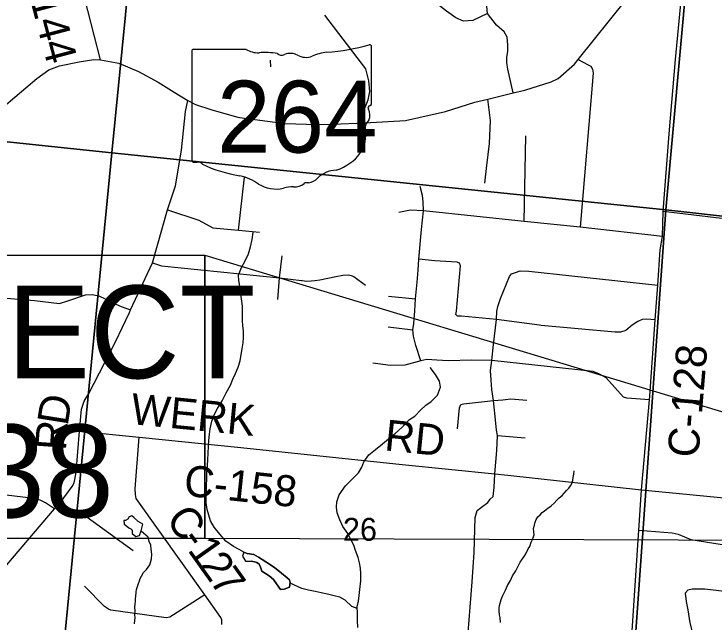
# Model space of a CAD drawing. Extents: x 0 to 34, y 0 to 22.
# Drawn here: x 4.767 to 6.05, y 18.737 to 19.852 of the extents above; entities that cross this region are included whole.
import ezdxf

# ---------------------------------------------------------------- set-up
doc = ezdxf.new("R2010")
doc.units = 0
for name, color, linetype in [('GM_X_Corporation', 7, 'Continuous'), ('GM_X_County_Road', 7, 'Continuous'), ('GM_X_County_Road_Text', 7, 'Continuous'), ('GM_X_Minor_Lake', 7, 'Continuous'), ('GM_X_Minor_River', 7, 'Continuous'), ('GM_X_Section_Text', 7, 'Continuous'), ('GM_X_State_Location', 7, 'Continuous'), ('GM_X_State_Route', 7, 'Continuous'), ('GM_X_State_Shield', 7, 'Continuous'), ('GM_X_Township_Road', 7, 'Continuous'), ('SH_Masking', 7, 'Continuous'), ('SH_Text', 7, 'Continuous')]:
    doc.layers.add(name, color=color, linetype=linetype)

msp = doc.modelspace()

# ---------------------------------------------------------------- linework, layer by layer
at = {"layer": 'GM_X_Corporation'}
for points in [[(4.0476, 20.7082), (5.0456, 20.6041), (4.9462, 19.5973), (3.9403, 19.7031)], [(6.0521, 20.4929), (5.9616, 19.4927), (4.9462, 19.5973), (5.0456, 20.6041)], [(7.0465, 20.3953), (6.9413, 19.3834), (5.9616, 19.4927), (6.0521, 20.4929)], [(3.9403, 19.7031), (4.9462, 19.5973), (4.8473, 18.5791), (3.8378, 18.696)], [(5.9616, 19.4927), (5.8893, 18.4792), (4.8473, 18.5791), (4.9462, 19.5973)], [(5.9616, 19.4927), (6.9413, 19.3834), (6.8431, 18.3799), (5.8893, 18.4792)]]:
    msp.add_lwpolyline(points, close=True, dxfattribs=at)
at = {"layer": 'GM_X_County_Road'}
for p, q in [((5.9168, 18.9788), (5.9863, 18.9721)), ((5.9863, 18.9721), (6.2648, 18.9452))]:
    msp.add_line(p, q, dxfattribs=at)
for points in [[(4.9258, 19.7674), (4.8794, 19.9495), (4.8769, 19.9594), (4.8389, 20.0979), (4.8359, 20.1136), (4.8327, 20.1338), (4.8321, 20.1419)], [(5.9168, 18.9788), (5.9313, 19.1438), (5.9319, 19.1508), (5.942, 19.291), (5.9466, 19.3546), (5.9513, 19.4191), (5.9555, 19.4438), (5.9566, 19.4892), (5.9673, 19.6321), (5.979, 19.7684), (6.0003, 19.9928)], [(4.8412, 18.9443), (4.8517, 18.9555), (4.8735, 18.985), (4.8771, 18.9917), (4.8807, 19.011), (4.8872, 19.0868), (4.8907, 19.127), (4.8957, 19.1417), (4.9044, 19.1555), (4.9529, 19.2503), (4.9786, 19.304), (4.9807, 19.309), (5.0206, 19.3955), (5.0483, 19.4923), (5.0629, 19.5365), (5.074, 19.602), (5.0812, 19.6731), (5.0855, 19.6928)], [(7.1544, 19.3549), (7.0147, 19.3697), (6.8713, 19.3848), (6.7437, 19.3982), (6.635, 19.4142), (6.3486, 19.4465), (6.2939, 19.453), (6.2651, 19.4538), (6.2278, 19.4581), (6.1978, 19.4615), (6.1234, 19.4701), (6.0534, 19.4781), (5.9566, 19.4892)], [(4.8872, 19.0868), (4.9964, 19.0755), (5.1827, 19.0567), (5.4785, 19.0256), (5.6484, 19.0085), (5.672, 19.0061), (5.9168, 18.9788)], [(5.148, 18.7319), (5.1476, 18.7405), (5.1462, 18.7448), (5.1166, 18.7862), (4.9908, 18.9634), (4.9895, 18.9703), (4.9891, 18.9809), (4.9964, 19.0755)], [(5.8839, 18.5182), (5.8859, 18.5217), (5.8895, 18.5379), (5.8981, 18.6884), (5.9, 18.7207), (5.912, 18.9053), (5.9168, 18.9788)], [(4.7476, 18.8343), (4.7539, 18.8418), (4.8412, 18.9443)]]:
    msp.add_lwpolyline(points, dxfattribs=at)
at = {"layer": 'GM_X_Minor_Lake'}
for points in [[(5, 18.9041), (5.0029, 18.9161), (4.9943, 18.9209), (4.9869, 18.9283), (4.9832, 18.9311), (4.9782, 18.9293), (4.9754, 18.9252), (4.9716, 18.923), (4.9685, 18.9227), (4.9691, 18.9159), (4.974, 18.9123), (4.9777, 18.9092), (4.981, 18.9076), (4.9833, 18.9049)], [(4.9833, 18.9049), (4.9835, 18.8992), (4.9902, 18.8937), (4.9971, 18.8954), (5, 18.9041)], [(5.1882, 18.8649), (5.1857, 18.8577), (5.1911, 18.848), (5.2018, 18.8481)], [(5.188, 18.865), (5.1941, 18.862), (5.2066, 18.8602), (5.2149, 18.8554), (5.2287, 18.8471), (5.2444, 18.8364), (5.2574, 18.8261), (5.2678, 18.8175), (5.2719, 18.814), (5.2733, 18.809), (5.2719, 18.8007), (5.262, 18.7971), (5.2555, 18.7962), (5.2478, 18.8066), (5.2427, 18.8148), (5.2345, 18.8214), (5.2281, 18.8254), (5.2214, 18.8298), (5.2186, 18.8374), (5.2161, 18.8428), (5.212, 18.8456), (5.2078, 18.8468), (5.2018, 18.8481)], [(5.2018, 18.8481), (5.2078, 18.8468), (5.212, 18.8456), (5.2161, 18.8428), (5.2186, 18.8374), (5.2214, 18.8298), (5.2281, 18.8254), (5.2345, 18.8214), (5.2427, 18.8148), (5.2478, 18.8066), (5.2555, 18.7962), (5.262, 18.7971), (5.2719, 18.8007), (5.2733, 18.809), (5.2719, 18.814), (5.2678, 18.8175), (5.2574, 18.8261), (5.2444, 18.8364), (5.2287, 18.8471), (5.2149, 18.8554), (5.2066, 18.8602), (5.1941, 18.862), (5.1882, 18.8649)]]:
    msp.add_lwpolyline(points, dxfattribs=at)
at = {"layer": 'GM_X_Minor_River'}
for points in [[(5.2375, 19.7551), (5.2371, 19.7672)], [(5.188, 18.865), (5.1796, 18.8696), (5.1695, 18.8752), (5.1554, 18.8847), (5.144, 18.898), (5.1337, 18.9104), (5.1269, 18.9224), (5.1241, 18.9324), (5.121, 18.9431), (5.1191, 18.9557), (5.119, 18.9664), (5.1197, 18.9774), (5.12, 18.9876), (5.1203, 18.9986), (5.1206, 19.0097), (5.1214, 19.0229), (5.1221, 19.0347), (5.1228, 19.0457), (5.1236, 19.0594), (5.1243, 19.0696), (5.1254, 19.0814), (5.1264, 19.0912), (5.1295, 19.1052), (5.1344, 19.118), (5.14, 19.1285), (5.1484, 19.1423), (5.156, 19.1569), (5.1637, 19.1708), (5.1678, 19.1821), (5.173, 19.1926), (5.1775, 19.2042), (5.1813, 19.2159), (5.1835, 19.2272), (5.185, 19.2375), (5.1868, 19.2484), (5.1875, 19.2583), (5.1878, 19.2705), (5.1866, 19.28), (5.1857, 19.2895), (5.1857, 19.3028), (5.1857, 19.3158), (5.1826, 19.3387), (5.1807, 19.3524), (5.1791, 19.3631), (5.1786, 19.373), (5.184, 19.3869), (5.1904, 19.3989), (5.1968, 19.412), (5.2006, 19.4248), (5.2037, 19.438), (5.2052, 19.4517)], [(5.3973, 18.7265), (5.3966, 18.7402), (5.3962, 18.7531), (5.3957, 18.7642), (5.398, 18.7751), (5.3994, 18.7854), (5.4008, 18.7963), (5.4024, 18.8119), (5.4024, 18.8248), (5.402, 18.8355), (5.4004, 18.8454), (5.3976, 18.855), (5.393, 18.868), (5.3899, 18.8776), (5.3841, 18.8881), (5.3787, 18.8989), (5.3693, 18.9121), (5.3639, 18.924), (5.3593, 18.9367), (5.3577, 18.947), (5.3588, 18.9572), (5.363, 18.97), (5.3744, 18.9864), (5.3873, 18.9994), (5.3983, 19.0105), (5.4043, 19.0206), (5.408, 19.0307), (5.4175, 19.0434), (5.4295, 19.0533), (5.442, 19.0632), (5.4533, 19.0724), (5.4657, 19.0823), (5.4786, 19.0941), (5.4919, 19.1078), (5.5016, 19.1144), (5.5121, 19.1251), (5.5219, 19.1343), (5.5316, 19.1409), (5.5429, 19.1527), (5.5483, 19.1674), (5.5467, 19.1785), (5.5395, 19.1908), (5.5296, 19.2037)], [(5.6586, 18.7359), (5.6578, 18.7447), (5.6568, 18.7496), (5.6563, 18.7565), (5.6561, 18.7622), (5.6566, 18.7671), (5.6597, 18.7777), (5.6622, 18.784), (5.6675, 18.7949), (5.6712, 18.8039), (5.6768, 18.8128), (5.6805, 18.8214), (5.6869, 18.8307), (5.6906, 18.8393), (5.6947, 18.8464), (5.6987, 18.8523), (5.7019, 18.8568), (5.7051, 18.8616), (5.7092, 18.8706), (5.712, 18.8751), (5.7146, 18.8833), (5.717, 18.8878), (5.7191, 18.8927), (5.72, 18.8968), (5.7194, 18.9018), (5.7192, 18.9079), (5.721, 18.9143), (5.7219, 18.9196), (5.724, 18.9244), (5.7268, 18.9293), (5.7311, 18.9333), (5.7347, 18.9377), (5.7393, 18.9406), (5.7452, 18.9454), (5.7514, 18.9497), (5.7569, 18.9548), (5.762, 18.96), (5.7663, 18.9644), (5.7714, 18.9688), (5.7754, 18.9728), (5.7797, 18.978), (5.7837, 18.982), (5.7869, 18.9865), (5.7897, 18.9917), (5.791, 18.9962), (5.7915, 19.0015), (5.7929, 19.0079), (5.7935, 19.014)], [(4.988, 18.7333), (4.9886, 18.7397), (4.9888, 18.745), (4.9886, 18.7496), (4.9888, 18.7572), (4.9887, 18.764), (4.9889, 18.7693), (4.9894, 18.7743), (4.9896, 18.7796), (4.9901, 18.7837), (4.9908, 18.7913), (4.9917, 18.7962), (4.9951, 18.8075), (4.9972, 18.812), (4.9985, 18.8165), (5.0009, 18.8206), (5.0042, 18.8273), (5.0101, 18.8328), (5.0157, 18.8414), (5.017, 18.8455), (5.0187, 18.8523), (5.0194, 18.861), (5.0186, 18.8702), (5.0177, 18.8774), (5.0149, 18.884), (5.0129, 18.892), (5.0003, 18.9031), (5, 18.9041)], [(5.3958, 18.7615), (5.3859, 18.7648), (5.3737, 18.7766), (5.364, 18.7822), (5.3538, 18.7848), (5.3417, 18.7878), (5.3297, 18.7904), (5.3191, 18.7926), (5.3066, 18.7949), (5.2942, 18.7983), (5.2731, 18.808)]]:
    msp.add_lwpolyline(points, dxfattribs=at)
at = {"layer": 'GM_X_State_Route'}
msp.add_line((5.1803, 19.6621), (5.2595, 19.6516), dxfattribs=at)
for points in [[(5.2595, 19.6516), (5.2635, 19.6511), (5.323, 19.6493), (5.3504, 19.6498), (5.4101, 19.652), (5.4843, 19.6566), (5.5575, 19.6731), (5.6113, 19.6898), (5.6351, 19.6956), (5.6817, 19.707), (5.7032, 19.7123), (5.7513, 19.7272), (5.7644, 19.7337), (5.7938, 19.7596), (5.8011, 19.7684), (5.8884, 19.8772), (5.9191, 19.9097)], [(4.7486, 19.6823), (4.8086, 19.7337), (4.8306, 19.7491), (4.8501, 19.7567), (4.8866, 19.7638), (4.9133, 19.7685), (4.9258, 19.7674), (4.9594, 19.7617), (4.9954, 19.7465), (5.0314, 19.7267), (5.0605, 19.7084)], [(5.0605, 19.7084), (5.0855, 19.6928), (5.0998, 19.686), (5.1295, 19.6758), (5.1773, 19.6625), (5.1803, 19.6621)]]:
    msp.add_lwpolyline(points, dxfattribs=at)
at = {"layer": 'GM_X_State_Shield'}
for p, q in [((5.0926, 19.7835), (5.0926, 19.5833)), ((5.1924, 19.7869), (5.0959, 19.7869)), ((5.4222, 19.6872), (5.4222, 19.7919)), ((5.4222, 19.6872), (5.4222, 19.6872))]:
    msp.add_line(p, q, dxfattribs=at)
for centre, major_axis, start_param, end_param in [((5.3048, 20.0597), (0.3495, 0), 4.814394, 5.042369), ((5.4185, 19.7923), (0.00367, 0), 6.141152, 7.989035), ((5.0964, 19.7839), (0.00382, 0), 1.712693, 3.28349), ((5.2154, 19.8101), (0.037, 0), 4.042523, 4.731795), ((5.2276, 19.6746), (0.133, 0), 1.404758, 1.657858), ((5.2578, 19.7849), (0.0107, 0), 3.836095, 5.185415), ((5.2735, 19.7618), (0.0222, 0), 0.950623, 2.079405), ((5.3494, 19.7258), (0.0703, 0), 1.699011, 2.107814), ((5.3022, 19.7935), (0.0267, 0), 4.081561, 5.145723), ((5.4213, 19.6795), (0.00568, 0), 1.883978, 3.671073), ((5.3852, 19.6663), (0.0341, 0), 5.934695, 6.695948), ((5.4183, 19.6868), (0.00393, 0), 5.05454, 6.418171), ((5.4353, 19.6434), (0.0248, 0), 2.387724, 3.262537), ((5.3244, 19.6301), (0.0874, 0), 5.101752, 6.440018), ((5.0964, 19.5829), (0.00385, 0), 3.00124, 4.508301), ((5.097, 19.6034), (0.0294, 0), 4.665946, 4.897461), ((5.103, 19.5718), (0.0106, 0), 0.519207, 1.627899), ((5.2368, 19.7516), (0.2524, 0), 4.195997, 4.488961), ((5.3612, 19.5272), (0.0479, 0), 1.647645, 2.488434), ((5.1616, 19.4934), (0.079, 0), 0.823519, 1.323587), ((5.3006, 19.5639), (0.0282, 0), 4.937069, 5.64225), ((5.247, 19.5708), (0.0501, 0), 4.026481, 4.996735), ((5.2796, 19.5558), (0.0267, 0), 4.691044, 5.507374), ((5.3038, 19.5364), (0.00752, 0), 1.147584, 2.315152), ((5.276, 19.5016), (0.0412, 0), 1.495662, 1.94098)]:
    msp.add_ellipse(centre, major_axis=major_axis, ratio=0.8, start_param=start_param, end_param=end_param, dxfattribs=at)
at = {"layer": 'GM_X_Township_Road'}
for p, q in [((5.702, 19.4712), (5.7049, 19.6284)), ((5.1785, 19.4554), (5.1897, 19.5526)), ((5.5381, 19.3991), (5.509, 19.4018)), ((5.4534, 19.3341), (5.5028, 19.3295)), ((5.4528, 19.2778), (5.4981, 19.2724)), ((5.6529, 19.0788), (5.7034, 19.0742))]:
    msp.add_line(p, q, dxfattribs=at)
for points in [[(5.6817, 19.707), (5.672, 19.7508), (5.6699, 19.7626), (5.6704, 19.772), (5.6717, 19.7838), (5.6722, 19.7954), (5.6706, 19.8093), (5.6653, 19.8189), (5.651, 19.8312), (5.6346, 19.8526), (5.6323, 19.8804), (5.6346, 19.926), (5.6387, 19.9552)], [(5.6346, 19.8526), (5.6081, 19.8399), (5.591, 19.8388), (5.5767, 19.8444), (5.5594, 19.8572), (5.5266, 19.8832), (5.5042, 19.9028), (5.4837, 19.9178), (5.4802, 19.9202)], [(5.4101, 19.652), (5.4069, 19.6719), (5.416, 19.6942), (5.4188, 19.7097), (5.4174, 19.7289), (5.4119, 19.7512), (5.3363, 19.8497)], [(5.8011, 19.7684), (5.8191, 19.7584), (5.8239, 19.756), (5.8271, 19.7505), (5.828, 19.7433), (5.8045, 19.4607)], [(5.63, 19.5414), (5.6332, 19.5736), (5.6381, 19.6145), (5.64, 19.6566), (5.6351, 19.6956)], [(5.5057, 19.3602), (5.5077, 19.3817), (5.509, 19.4018), (5.5137, 19.4565), (5.5175, 19.4906), (5.5167, 19.5075), (5.5154, 19.5189), (5.5112, 19.5354)], [(5.0483, 19.4923), (5.1056, 19.4736), (5.1311, 19.4595), (5.1785, 19.4554), (5.2168, 19.4518)], [(5.9555, 19.4438), (5.8045, 19.4607), (5.702, 19.4712), (5.5175, 19.4906), (5.4938, 19.4918), (5.4724, 19.4878)], [(5.2502, 19.3279), (5.2537, 19.3677), (5.2587, 19.408)], [(5.0206, 19.3955), (5.0372, 19.3901), (5.2537, 19.3677), (5.294, 19.3629), (5.295, 19.3628)], [(5.7301, 19.2811), (5.6509, 19.2916), (5.5871, 19.2978), (5.5794, 19.2978), (5.5768, 19.3009), (5.5776, 19.3067), (5.5851, 19.3896), (5.5831, 19.3945), (5.5791, 19.3963), (5.5478, 19.3983), (5.5381, 19.3991)], [(5.295, 19.3628), (5.3037, 19.3619), (5.3117, 19.3622), (5.3184, 19.3627), (5.3273, 19.3639), (5.3566, 19.3704), (5.3696, 19.3727), (5.3802, 19.3736), (5.3848, 19.3724), (5.39, 19.3703), (5.4112, 19.3541)], [(5.6509, 19.2916), (5.6518, 19.3066), (5.6539, 19.315), (5.6587, 19.3297), (5.6748, 19.3703), (5.6788, 19.3751), (5.6857, 19.3775), (5.6945, 19.3806), (5.7104, 19.3801), (5.9466, 19.3546)], [(5.5125, 19.2156), (5.5032, 19.2438), (5.499, 19.261), (5.4981, 19.2724), (5.4996, 19.2844), (5.5017, 19.3075), (5.5028, 19.3295), (5.5057, 19.3602)], [(4.7054, 19.3059), (4.704, 19.3211), (4.7077, 19.336), (4.746, 19.331), (4.8048, 19.326), (4.8504, 19.3205), (4.8654, 19.3255), (4.8982, 19.3369), (4.9101, 19.3374), (4.9224, 19.3351), (4.9356, 19.3287), (4.9481, 19.3222), (4.9634, 19.315), (4.9807, 19.309)], [(5.942, 19.291), (5.9261, 19.2919), (5.918, 19.2913), (5.9099, 19.288), (5.8998, 19.2808), (5.8881, 19.2713), (5.8781, 19.2684), (5.8686, 19.2683), (5.7331, 19.2807), (5.7301, 19.2811)], [(5.5995, 18.7171), (5.6067, 18.8106), (5.6105, 18.8641), (5.6122, 18.9282), (5.616, 18.941), (5.6238, 18.9472), (5.6355, 18.9556), (5.6398, 18.9619), (5.6451, 18.9669), (5.6466, 18.9834), (5.6484, 19.0085), (5.6517, 19.0512), (5.6529, 19.0788), (5.6514, 19.0885), (5.6502, 19.1014), (5.6456, 19.1428), (5.6428, 19.1629), (5.6413, 19.1799), (5.6404, 19.1979), (5.6425, 19.2162), (5.6455, 19.2456), (5.6509, 19.2916)], [(5.5421, 19.217), (5.5233, 19.218), (5.5125, 19.2156), (5.4831, 19.2075), (5.457, 19.2072), (5.4247, 19.2115)], [(5.9313, 19.1438), (5.8901, 19.1472), (5.8837, 19.1489), (5.8519, 19.1845), (5.8399, 19.1914), (5.8285, 19.1963), (5.6425, 19.2162), (5.6057, 19.2167), (5.5629, 19.2159), (5.5421, 19.217)], [(5.5798, 19.0912), (5.5832, 19.1293), (5.5858, 19.1353), (5.591, 19.1366), (5.6456, 19.1428), (5.6628, 19.1443), (5.6776, 19.1458), (5.7068, 19.1432)], [(4.8412, 18.9443), (4.8247, 18.9555), (4.8152, 18.9604), (4.8031, 18.9631), (4.6459, 18.9821), (4.591, 18.9883)], [(4.8517, 18.9555), (4.8587, 18.9494), (4.8733, 18.9428), (4.8876, 18.9386), (4.9851, 18.8678)], [(5.912, 18.9053), (5.973, 18.8999), (5.9843, 18.898), (6.0075, 18.8882), (6.0916, 18.8748), (6.1165, 18.8706), (6.1266, 18.8684), (6.1348, 18.8639), (6.1403, 18.8569), (6.1585, 18.7993), (6.1609, 18.7918), (6.1681, 18.769), (6.1714, 18.7644), (6.1765, 18.7593), (6.2206, 18.7408)], [(5.1166, 18.7862), (5.0523, 18.7456), (5.0458, 18.744), (4.9443, 18.7582), (4.9402, 18.7599), (4.9328, 18.7651), (4.8965, 18.8023)], [(6.104, 18.7883), (6.1021, 18.7885), (6.0844, 18.7905), (6.0329, 18.7966), (6.0168, 18.7971), (6.0099, 18.7967), (6.0019, 18.7952), (5.9971, 18.7897)], [(5.9971, 18.7897), (5.9988, 18.7743), (6.0016, 18.7591), (6.0053, 18.735), (6.0271, 18.6522), (6.0409, 18.5926)]]:
    msp.add_lwpolyline(points, dxfattribs=at)
at = {"layer": 'SH_Masking'}
msp.add_lwpolyline([(3.3595, 19.4095), (5.117, 19.4095), (5.117, 18.89), (3.3595, 18.89)], close=True, dxfattribs=at)
at = {"layer": 'SH_Text'}
for points in [[(3.3595, 19.4095), (5.117, 19.4095), (5.117, 18.89), (3.3595, 18.89)], [(5.117, 19.4095), (6.8528, 18.8836), (5.117, 18.89)]]:
    msp.add_lwpolyline(points, close=True, dxfattribs=at)

# ---------------------------------------------------------------- texts
at = {"layer": 'GM_X_County_Road_Text'}
for s, height, rotation, p in [('C-144', 0.05682, 284.8258, (4.7755, 19.957)), ('C-128', 0.05682, 85.3275, (6.021, 19.0369)), ('D', 0.0568, 80.9539, (4.8653, 19.0951)), ('WERK', 0.05682, 354.4546, (4.9792, 19.0998)), ('R', 0.0568, 85.8454, (4.862, 19.0499)), ('RD', 0.05682, 354.1938, (5.4445, 19.0516)), ('C-158', 0.05682, 353.9906, (5.0766, 18.9687)), ('C', 0.0568, 305.3822, (5.0437, 18.9253)), ('-', 0.0568, 305.3823, (5.0705, 18.8876)), ('1', 0.0568, 305.3825, (5.0839, 18.8687)), ('2', 0.0568, 305.3916, (5.104, 18.8404)), ('7', 0.0568, 305.441, (5.1241, 18.812))]:
    msp.add_text(s, height=height, rotation=rotation, dxfattribs=at).set_placement(p)
at = {"layer": 'GM_X_Section_Text'}
msp.add_text('26', height=0.04186, rotation=0, dxfattribs=at).set_placement((5.3698, 18.8857))
at = {"layer": 'GM_X_State_Location'}
for s in ['s', 'r']:
    msp.add_text(s, height=0.000189, dxfattribs=at).set_placement((5.2537, 19.6701))
msp.add_text('264', height=0.000189, rotation=0, dxfattribs=at).set_placement((5.1868, 19.6563))
at = {"layer": 'GM_X_State_Shield'}
msp.add_text('264', height=0.13184, dxfattribs=at).set_placement((5.1391, 19.5975))
at = {"layer": 'SH_Text'}
for s, p in [('BEGIN PROJECT', (3.3778, 19.1837)), ('STA. 54.47.38', (3.4967, 18.9287))]:
    msp.add_text(s, height=0.17, dxfattribs=at).set_placement(p)

doc.saveas('drawing.dxf')
